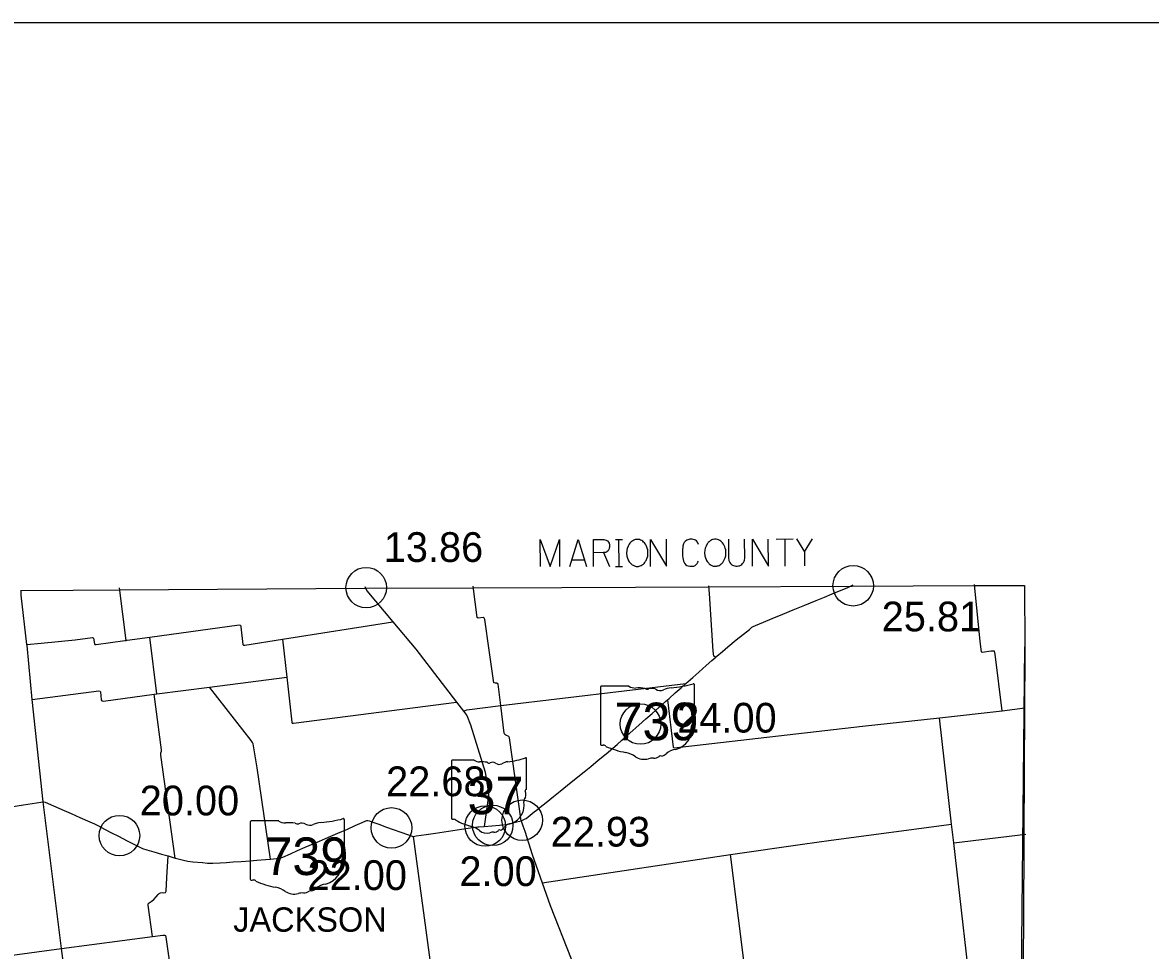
# Model space of a CAD drawing. Extents: x 1659811 to 1934326, y 644115 to 934867.
# Drawn here: x 1723269 to 1765018, y 900512 to 934867 of the extents above; entities that cross this region are included whole.
import ezdxf

# ---------------------------------------------------------------- set-up
doc = ezdxf.new("R2010")
doc.units = 0
for name, color, linetype in [('Default', 7, 'Continuous'), ('GM_X_Adjacent_County', 7, 'Continuous'), ('GM_X_Adjacent_County_Text', 7, 'Continuous'), ('GM_X_County', 7, 'Continuous'), ('GM_X_County_Road', 7, 'Continuous'), ('GM_X_State_Route', 7, 'Continuous'), ('GM_X_State_Shield', 7, 'Continuous'), ('GM_X_Township_Road', 7, 'Continuous'), ('GM_X_Township_Text', 7, 'Continuous'), ('SC_Scratch1', 7, 'Continuous')]:
    doc.layers.add(name, color=color, linetype=linetype)

msp = doc.modelspace()

# ---------------------------------------------------------------- linework, layer by layer
at = {"layer": 'Default'}
for centre in [(1754015, 914014), (1754015, 914014), (1735989, 913944), (1735989, 913944), (1746142, 908896), (1741763, 905335), (1736926, 905049), (1740394, 905118), (1740671, 905144), (1726856, 904763)]:
    msp.add_circle(centre, 750, dxfattribs=at)
at = {"layer": 'GM_X_Adjacent_County'}
msp.add_line((1760161, 891042), (1760364, 911751), dxfattribs=at)
at = {"layer": 'GM_X_Adjacent_County_Text'}
for p, q in [((1745219, 915730), (1745471, 915730)), ((1745347, 914730), (1745345, 915730)), ((1751168, 915744), (1751790, 915746)), ((1751483, 915745), (1751485, 914745)), ((1744776, 915240), (1744998, 914729)), ((1752216, 915266), (1752218, 914747)), ((1744066, 914963), (1743601, 914962)), ((1745221, 914730), (1745473, 914730))]:
    msp.add_line(p, q, dxfattribs=at)
for points in [[(1742436, 914723), (1742434, 915723), (1742798, 914724), (1743142, 915725), (1743145, 914725)], [(1743523, 914726), (1743835, 915726), (1744145, 914727)], [(1744407, 914728), (1744405, 915728), (1744783, 915729), (1744822, 915721), (1744877, 915705), (1744901, 915689), (1744925, 915674), (1744956, 915634), (1744980, 915595), (1744996, 915532), (1744996, 915438), (1744988, 915406), (1744973, 915359), (1744941, 915304), (1744910, 915280), (1744886, 915264), (1744871, 915256), (1744847, 915248), (1744776, 915240), (1744406, 915239)], [(1745943, 915723), (1745919, 915715), (1745896, 915708), (1745857, 915684), (1745833, 915668), (1745794, 915636), (1745762, 915605), (1745747, 915589), (1745723, 915558), (1745684, 915479), (1745653, 915400), (1745637, 915329), (1745629, 915227), (1745637, 915116), (1745661, 915038), (1745685, 914975), (1745701, 914943), (1745725, 914904), (1745756, 914865), (1745780, 914841), (1745804, 914818), (1745835, 914794), (1745875, 914771), (1745946, 914739), (1745985, 914732), (1746064, 914732), (1746095, 914740), (1746127, 914748), (1746166, 914763), (1746205, 914787), (1746229, 914803), (1746252, 914819), (1746276, 914842), (1746299, 914874), (1746315, 914898), (1746331, 914921), (1746347, 914945), (1746370, 914992), (1746393, 915047), (1746409, 915110), (1746417, 915166), (1746417, 915173), (1746417, 915229), (1746417, 915276), (1746409, 915339), (1746393, 915402), (1746377, 915449), (1746353, 915504), (1746329, 915551), (1746290, 915598), (1746258, 915630), (1746227, 915661), (1746195, 915685), (1746148, 915708), (1746101, 915724), (1746053, 915732), (1745998, 915732), (1745943, 915723)], [(1746515, 914733), (1746513, 915733), (1747105, 914734), (1747103, 915734)], [(1748292, 915540), (1748252, 915627), (1748213, 915674), (1748173, 915705), (1748142, 915721), (1748055, 915737), (1747968, 915736), (1747858, 915704), (1747795, 915657), (1747764, 915618), (1747733, 915562), (1747709, 915476), (1747702, 915318), (1747702, 915200), (1747702, 915121), (1747710, 915051), (1747734, 914925), (1747742, 914901), (1747774, 914846), (1747805, 914807), (1747860, 914768), (1747908, 914752), (1747971, 914736), (1748042, 914736), (1748112, 914744), (1748136, 914752), (1748167, 914768), (1748199, 914800), (1748238, 914839), (1748270, 914887), (1748293, 914926)], [(1748830, 915730), (1748806, 915722), (1748782, 915715), (1748743, 915691), (1748720, 915675), (1748680, 915643), (1748649, 915612), (1748633, 915596), (1748610, 915565), (1748570, 915486), (1748539, 915407), (1748523, 915336), (1748516, 915234), (1748524, 915123), (1748548, 915045), (1748572, 914982), (1748587, 914950), (1748611, 914911), (1748643, 914872), (1748666, 914848), (1748690, 914825), (1748722, 914801), (1748761, 914778), (1748832, 914746), (1748871, 914738), (1748950, 914739), (1748982, 914747), (1749013, 914755), (1749052, 914770), (1749092, 914794), (1749115, 914810), (1749139, 914826), (1749162, 914849), (1749186, 914881), (1749202, 914905), (1749217, 914928), (1749233, 914952), (1749257, 914999), (1749280, 915054), (1749296, 915117), (1749303, 915173), (1749303, 915180), (1749303, 915235), (1749303, 915283), (1749295, 915346), (1749279, 915409), (1749263, 915456), (1749240, 915511), (1749216, 915558), (1749176, 915605), (1749145, 915637), (1749113, 915668), (1749082, 915692), (1749034, 915715), (1748987, 915731), (1748940, 915739), (1748885, 915739), (1748830, 915730)], [(1749399, 915740), (1749401, 915039), (1749409, 914968), (1749417, 914945), (1749433, 914905), (1749448, 914874), (1749472, 914842), (1749488, 914827), (1749496, 914819), (1749527, 914795), (1749551, 914779), (1749582, 914764), (1749630, 914748), (1749677, 914740), (1749724, 914741), (1749771, 914748), (1749803, 914756), (1749850, 914780), (1749890, 914804), (1749921, 914835), (1749952, 914875), (1749976, 914922), (1749991, 914962), (1749999, 915040), (1749997, 915741)], [(1750286, 914742), (1750284, 915742), (1750876, 914743), (1750874, 915743)], [(1751916, 915746), (1752216, 915266), (1752514, 915747)]]:
    msp.add_lwpolyline(points, dxfattribs=at)
at = {"layer": 'GM_X_County'}
msp.add_lwpolyline([(1723205, 913838), (1725148, 913846), (1726840, 913858), (1735953, 913922), (1739940, 913938), (1743227, 913952), (1748682, 913976), (1753982, 914000), (1758493, 914019), (1759934, 914025), (1760358, 914021), (1760364, 911751), (1760364, 911476), (1760357, 909471), (1760334, 904783), (1760318, 901515), (1760281, 898058)], dxfattribs=at)
at = {"layer": 'GM_X_County_Road'}
for points in [[(1740970, 909576), (1740869, 910372), (1740827, 910413), (1740761, 910413), (1740717, 910420), (1740535, 911630), (1740379, 912762), (1740354, 912819), (1740322, 912837), (1740133, 912818), (1740095, 912838), (1739953, 913996)], [(1748929, 911373), (1748852, 911406), (1748836, 911587), (1748698, 913730), (1748676, 914010)], [(1724026, 906020), (1723624, 909802), (1723436, 911803), (1723431, 911843), (1723214, 913667), (1723218, 913847)], [(1732896, 912032), (1736979, 912677)], [(1727978, 912117), (1731292, 912568), (1731332, 912555), (1731350, 912497), (1731424, 911845), (1731444, 911813), (1731502, 911812), (1732896, 912032)], [(1728241, 910016), (1727978, 912117)], [(1732896, 912032), (1733051, 910628), (1733232, 908968), (1733247, 908930), (1733295, 908925), (1739337, 909708)], [(1728241, 910016), (1730194, 910261), (1733051, 910628)], [(1732449, 903896), (1731955, 907269), (1731802, 908157), (1731785, 908210), (1731737, 908286), (1730194, 910261)], [(1739593, 909377), (1739709, 909425), (1740970, 909576), (1747822, 910399)], [(1723624, 909802), (1726098, 910124), (1726142, 910114), (1726149, 910082), (1726177, 909787), (1726201, 909749), (1726260, 909744), (1728135, 910001), (1728241, 910016)], [(1747138, 909789), (1747347, 908043), (1747361, 908021), (1747393, 908019), (1754359, 908811), (1757209, 909119), (1759533, 909389), (1760364, 909493)], [(1741730, 905315), (1741299, 908379), (1741267, 908434), (1741157, 908477), (1741118, 908505), (1741100, 908551), (1740970, 909576)], [(1758488, 897881), (1757735, 904494), (1757656, 905193), (1757209, 909119)], [(1725630, 893897), (1724990, 898451), (1724709, 900587), (1724026, 906020)], [(1742507, 903012), (1749478, 904070), (1752136, 904446), (1753199, 904591), (1757656, 905193)], [(1738987, 895592), (1738584, 898536), (1738461, 899435), (1737736, 904736)], [(1728076, 901028), (1727919, 902184), (1727924, 902234), (1727956, 902275), (1728025, 902319), (1728123, 902396), (1728216, 902495), (1728283, 902587), (1728323, 902621), (1728381, 902646), (1728443, 902652), (1728497, 902641), (1728559, 902657), (1728578, 902681), (1728588, 902711), (1728614, 903207), (1728658, 904011)], [(1750363, 896999), (1749478, 904070)], [(1718117, 899769), (1720962, 900082), (1724709, 900587), (1728076, 901028), (1728466, 901079), (1728522, 901084), (1728556, 901068), (1728576, 901004), (1729525, 894413)]]:
    msp.add_lwpolyline(points, dxfattribs=at)
at = {"layer": 'GM_X_State_Route'}
for points in [[(1735941, 913992), (1736017, 913830), (1736979, 912677), (1737827, 911661), (1739337, 909708), (1739593, 909377), (1739719, 909214), (1739854, 908867), (1740391, 907110), (1740521, 906331), (1740520, 906235), (1740361, 905098)], [(1742373, 905771), (1742425, 905814), (1742646, 905990), (1742920, 906211), (1743168, 906409), (1743446, 906635), (1743760, 906889), (1744053, 907125), (1744300, 907328), (1744578, 907558), (1744871, 907795), (1745118, 907997), (1745279, 908142), (1745448, 908297), (1745653, 908476), (1745864, 908660), (1746086, 908859), (1746342, 909084), (1746572, 909288), (1746824, 909510), (1747072, 909732), (1747138, 909789), (1747202, 909844), (1747427, 910048), (1747647, 910238), (1747822, 910399), (1748080, 910617), (1748307, 910821), (1748571, 911059), (1748779, 911245), (1748929, 911373), (1748970, 911408), (1749173, 911580), (1749376, 911759), (1749687, 912007), (1749956, 912224), (1750172, 912400), (1750268, 912476), (1750308, 912506), (1750401, 912544), (1750694, 912666), (1751017, 912800), (1751411, 912966), (1751799, 913128), (1752221, 913300), (1752639, 913470), (1752954, 913598), (1753235, 913714), (1753576, 913848), (1753789, 913933), (1754018, 914050)], [(1722836, 905826), (1723307, 905902), (1723790, 905981), (1724026, 906020), (1724062, 906019), (1724107, 906002), (1724414, 905872), (1724806, 905699), (1725067, 905580), (1725392, 905438), (1725757, 905279), (1725926, 905204), (1726077, 905125), (1726307, 905005), (1726562, 904870), (1726816, 904741), (1727143, 904573), (1727482, 904397), (1727629, 904320), (1727711, 904291), (1727874, 904240), (1728123, 904169), (1728409, 904082), (1728658, 904011), (1728918, 903934), (1728976, 903917), (1729223, 903849), (1729383, 903816), (1729576, 903796), (1729926, 903768), (1730120, 903748), (1730314, 903749), (1730580, 903754), (1730824, 903768), (1731059, 903787), (1731357, 903810), (1731688, 903834), (1731936, 903858), (1732265, 903880), (1732449, 903896), (1732778, 903925), (1732828, 903936), (1732903, 903970), (1733193, 904093), (1733441, 904207), (1733727, 904332), (1734022, 904461), (1734260, 904563), (1734594, 904705), (1734945, 904859), (1735294, 905008), (1735584, 905137), (1735844, 905253), (1735973, 905307), (1736012, 905318), (1736050, 905319), (1736103, 905306), (1736239, 905260), (1736453, 905182), (1736738, 905080), (1736982, 904996), (1737267, 904895), (1737549, 904791), (1737692, 904745), (1737736, 904736), (1737836, 904752), (1738203, 904806), (1738558, 904859), (1738873, 904906), (1739194, 904954), (1739517, 904998), (1739848, 905047), (1740117, 905084), (1740163, 905086), (1740361, 905098)], [(1741730, 905315), (1741879, 905381), (1741915, 905402), (1741988, 905459), (1742212, 905639), (1742373, 905771)], [(1740361, 905098), (1741205, 905177), (1741246, 905187)], [(1741246, 905187), (1741307, 905204), (1741418, 905233), (1741568, 905272), (1741730, 905315)], [(1741730, 905315), (1741792, 905123), (1741855, 904929), (1742136, 904059), (1742507, 903012), (1742804, 902172), (1743577, 900206), (1744035, 899052), (1744303, 898377), (1745121, 896342), (1746092, 893887), (1746206, 893597), (1746478, 891502), (1746693, 889882)]]:
    msp.add_lwpolyline(points, dxfattribs=at)
at = {"layer": 'GM_X_State_Shield'}
for p, q in [((1744657, 910258), (1744657, 908145)), ((1745711, 910294), (1744692, 910294)), ((1748138, 909241), (1748138, 910347)), ((1748137, 909242), (1748138, 909241)), ((1739141, 907521), (1739141, 905408)), ((1739984, 907558), (1739169, 907558)), ((1741926, 906505), (1741926, 907610)), ((1741925, 906505), (1741926, 906505)), ((1731699, 905268), (1731699, 903155)), ((1732753, 905305), (1731734, 905305)), ((1735180, 904252), (1735180, 905357)), ((1735179, 904252), (1735180, 904252))]:
    msp.add_line(p, q, dxfattribs=at)
for centre, radius, start, end in [((1740934, 910439), 2953, 275.8445, 288.9065), ((1741895, 907615), 31, 351.8621, 97.738), ((1739173, 907526), 32.3, 98.1301, 188.1301), ((1740178, 907803), 313, 231.6195, 271.1119), ((1740282, 906371), 1123, 80.4867, 94.9883), ((1740537, 907537), 90.3, 219.7921, 297.1024), ((1740669, 907292), 188, 54.4667, 119.1411), ((1740912, 907627), 226, 233.8562, 294.8282), ((1741310, 906912), 594, 97.3462, 120.7689), ((1741918, 906423), 48, 107.944, 210.337), ((1741613, 906284), 288, 340.033, 23.6496), ((1741893, 906500), 33.2, 289.6038, 7.7341), ((1741099, 905901), 739, 292.3089, 8.9858), ((1742037, 906042), 210, 136.8065, 186.9296), ((1739173, 905403), 32.5, 171.9584, 258.3066), ((1739178, 905620), 248, 267.339, 280.6039), ((1739229, 905286), 89.5, 29.7484, 93.2717), ((1740360, 907185), 2132, 240.4129, 257.1985), ((1741411, 904815), 404, 94.4031, 142.5768), ((1739724, 904459), 667, 47.1842, 75.836), ((1740446, 905276), 423, 230.7004, 286.2918), ((1740690, 904545), 348, 85.6951, 111.2099), ((1740721, 905117), 226, 268.777, 315.5493), ((1740925, 904913), 63.5, 65.7517, 132.6484), ((1740898, 905203), 239, 282.8732, 323.2771)]:
    msp.add_arc(centre, radius, start, end, dxfattribs=at)
for centre, major_axis, start_param, end_param in [((1744697, 910263), (40.3, 0), 1.712693, 3.28349), ((1745954, 910540), (391, 0), 4.042523, 4.731795), ((1746083, 909108), (1404, 0), 1.404758, 1.657858), ((1746402, 910274), (113, 0), 3.836095, 5.185415), ((1746568, 910029), (235, 0), 0.950623, 2.079405), ((1746870, 910364), (282, 0), 4.081561, 5.145723), ((1747369, 909649), (743, 0), 1.699011, 2.107814), ((1746898, 913176), (3691, 0), 4.814394, 5.042369), ((1748099, 910351), (38.7, 0), 6.141152, 7.989035), ((1748277, 908779), (262, 0), 2.387724, 3.262537), ((1748129, 909160), (60, 0), 1.883978, 3.671073), ((1747747, 909020), (360, 0), 5.934695, 6.695948), ((1748096, 909237), (41.5, 0), 5.05454, 6.418171), ((1747105, 908638), (923, 0), 5.101752, 6.440018), ((1744698, 908140), (40.7, 0), 3.00124, 4.508301), ((1744704, 908356), (310, 0), 4.665946, 4.897461), ((1744767, 908023), (112, 0), 0.519207, 1.627899), ((1746180, 909922), (2665, 0), 4.195997, 4.488961), ((1745386, 907195), (834, 0), 0.823519, 1.323587), ((1746288, 908012), (529, 0), 4.026481, 4.996735), ((1746594, 907282), (435, 0), 1.495662, 1.94098), ((1746632, 907854), (282, 0), 4.691044, 5.507374), ((1746887, 907649), (79.4, 0), 1.147584, 2.315152), ((1746853, 907940), (298, 0), 4.937069, 5.64225), ((1747494, 907551), (506, 0), 1.647645, 2.488434), ((1731739, 905273), (40.3, 0), 1.712693, 3.28349), ((1732996, 905550), (391, 0), 4.042523, 4.731795), ((1733125, 904118), (1404, 0), 1.404758, 1.657858), ((1733444, 905284), (113, 0), 3.836095, 5.185415), ((1733610, 905040), (235, 0), 0.950623, 2.079405), ((1733912, 905375), (282, 0), 4.081561, 5.145723), ((1734411, 904659), (743, 0), 1.699011, 2.107814), ((1733940, 908186), (3691, 0), 4.814394, 5.042369), ((1735141, 905362), (38.7, 0), 6.141152, 7.989035), ((1735319, 903789), (262, 0), 2.387724, 3.262537), ((1735171, 904171), (60, 0), 1.883978, 3.671073), ((1734789, 904031), (360, 0), 5.934695, 6.695948), ((1735138, 904247), (41.5, 0), 5.05454, 6.418171), ((1734147, 903648), (923, 0), 5.101752, 6.440018), ((1731740, 903151), (40.7, 0), 3.00124, 4.508301), ((1731746, 903367), (310, 0), 4.665946, 4.897461), ((1731809, 903033), (112, 0), 0.519207, 1.627899), ((1733222, 904932), (2665, 0), 4.195997, 4.488961), ((1732428, 902206), (834, 0), 0.823519, 1.323587), ((1733330, 903023), (529, 0), 4.026481, 4.996735), ((1733636, 902292), (435, 0), 1.495662, 1.94098), ((1733674, 902865), (282, 0), 4.691044, 5.507374), ((1733929, 902660), (79.4, 0), 1.147584, 2.315152), ((1733895, 902950), (298, 0), 4.937069, 5.64225), ((1734536, 902562), (506, 0), 1.647645, 2.488434)]:
    msp.add_ellipse(centre, major_axis=major_axis, ratio=0.8, start_param=start_param, end_param=end_param, dxfattribs=at)
at = {"layer": 'GM_X_Township_Road'}
for points in [[(1727101, 911993), (1726858, 913937)], [(1759533, 909389), (1759267, 911482), (1759246, 911593), (1759196, 911598), (1759121, 911587), (1758790, 911543), (1758765, 911567), (1758717, 911946), (1758502, 914063)], [(1723431, 911843), (1723959, 911893), (1723960, 911893)], [(1723960, 911893), (1725212, 912012), (1725859, 912100), (1725885, 912090), (1725899, 912069), (1725934, 911861), (1725950, 911840), (1725988, 911844), (1727060, 911987), (1727101, 911993), (1727137, 911998)], [(1727137, 911998), (1727139, 911998), (1727978, 912117)], [(1728918, 903934), (1728386, 907737), (1728382, 907781), (1728393, 907827), (1728411, 907887), (1728406, 907939), (1728135, 910001)], [(1757735, 904494), (1760404, 904819)]]:
    msp.add_lwpolyline(points, dxfattribs=at)
at = {"layer": 'SC_Scratch1'}
msp.add_lwpolyline([(1659811, 738617), (1659811, 934867), (1794311, 934867), (1794311, 738617)], close=True, dxfattribs=at)

# ---------------------------------------------------------------- texts
at = {"layer": 'Default'}
for s, p in [('13.86', (1736638, 914897)), ('25.81', (1755070, 912326)), ('24.00', (1747501, 908579)), ('22.68', (1736726, 906224)), ('20.00', (1727606, 905513)), ('22.93', (1742818, 904358)), ('2.00', (1739440, 902897)), ('22.00', (1733816, 902751))]:
    msp.add_text(s, height=1100, dxfattribs=at).set_placement(p)
at = {"layer": 'GM_X_State_Shield'}
for s, p in [('739', (1745180, 908294)), ('37', (1739742, 905557)), ('739', (1732222, 903304))]:
    msp.add_text(s, height=1392.2, dxfattribs=at).set_placement(p)
at = {"layer": 'GM_X_Township_Text'}
msp.add_text('JACKSON', height=900, rotation=0, dxfattribs=at).set_placement((1731066, 901206))

doc.saveas('drawing.dxf')
